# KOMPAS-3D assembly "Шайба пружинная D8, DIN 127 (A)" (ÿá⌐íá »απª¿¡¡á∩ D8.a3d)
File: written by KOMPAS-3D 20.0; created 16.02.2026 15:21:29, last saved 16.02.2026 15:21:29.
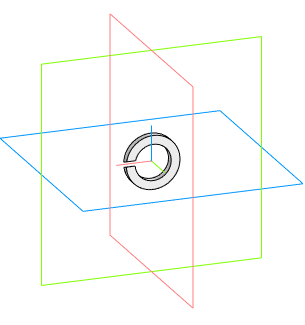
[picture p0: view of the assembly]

Document properties: Автор: admin; Полное имя файла: P:\INSTART\Технический отдел\ОР\Прочие задачи\КД на номенклатурный ряд\КД на типоразмеры дросселей\Сетевые дроссели ISF\ISF-4\Тип 1\ISF-132_256-4\0723\Новая папка\Шайба пружинная D8.a3d

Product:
- Part/product: Шайба пружинная D8  | designation DIN 127 (A)
  - Component [detail]: Шайба 2 8Л ГОСТ 6402-70  | source file: Шайба 2 8Л ГОСТ 6402-70.m3d

Referenced files in P:\INSTART\Технический отдел\ОР\Прочие задачи\КД на номенклатурный ряд\КД на типоразмеры дросселей\Сетевые дроссели ISF\ISF-4\Тип 1\ISF-132_256-4\0723\Новая папка\: Шайба 2 8Л ГОСТ 6402-70.m3d
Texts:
  DIN 127 (A)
